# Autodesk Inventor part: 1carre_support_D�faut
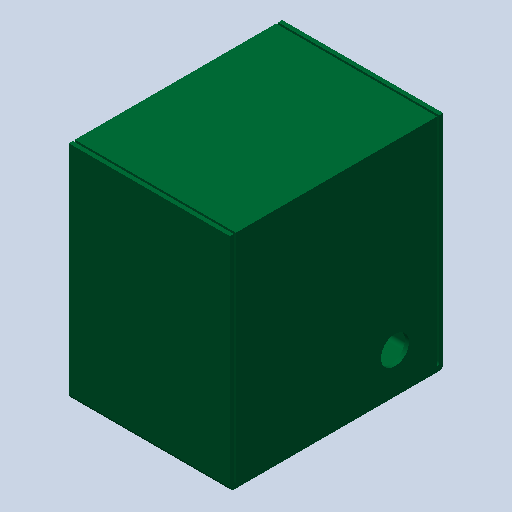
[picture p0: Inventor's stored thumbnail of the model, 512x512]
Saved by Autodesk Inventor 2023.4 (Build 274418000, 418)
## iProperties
Created: 2011-01
Part Number: 1carre_support_D�faut
Document SubType Name: Modeling
Designer: eric
Density: 1 g/cm^3
Mass: 13.663 g
Surface Area: 278.946 cm^2
Volume: 13.663 cm^3
Material: Générique
Appearance: 0,128,64_1
Author: eric
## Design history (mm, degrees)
feature "Base1"
node "Corps solides"
node "Corps surfaciques"
node "Solide1"
